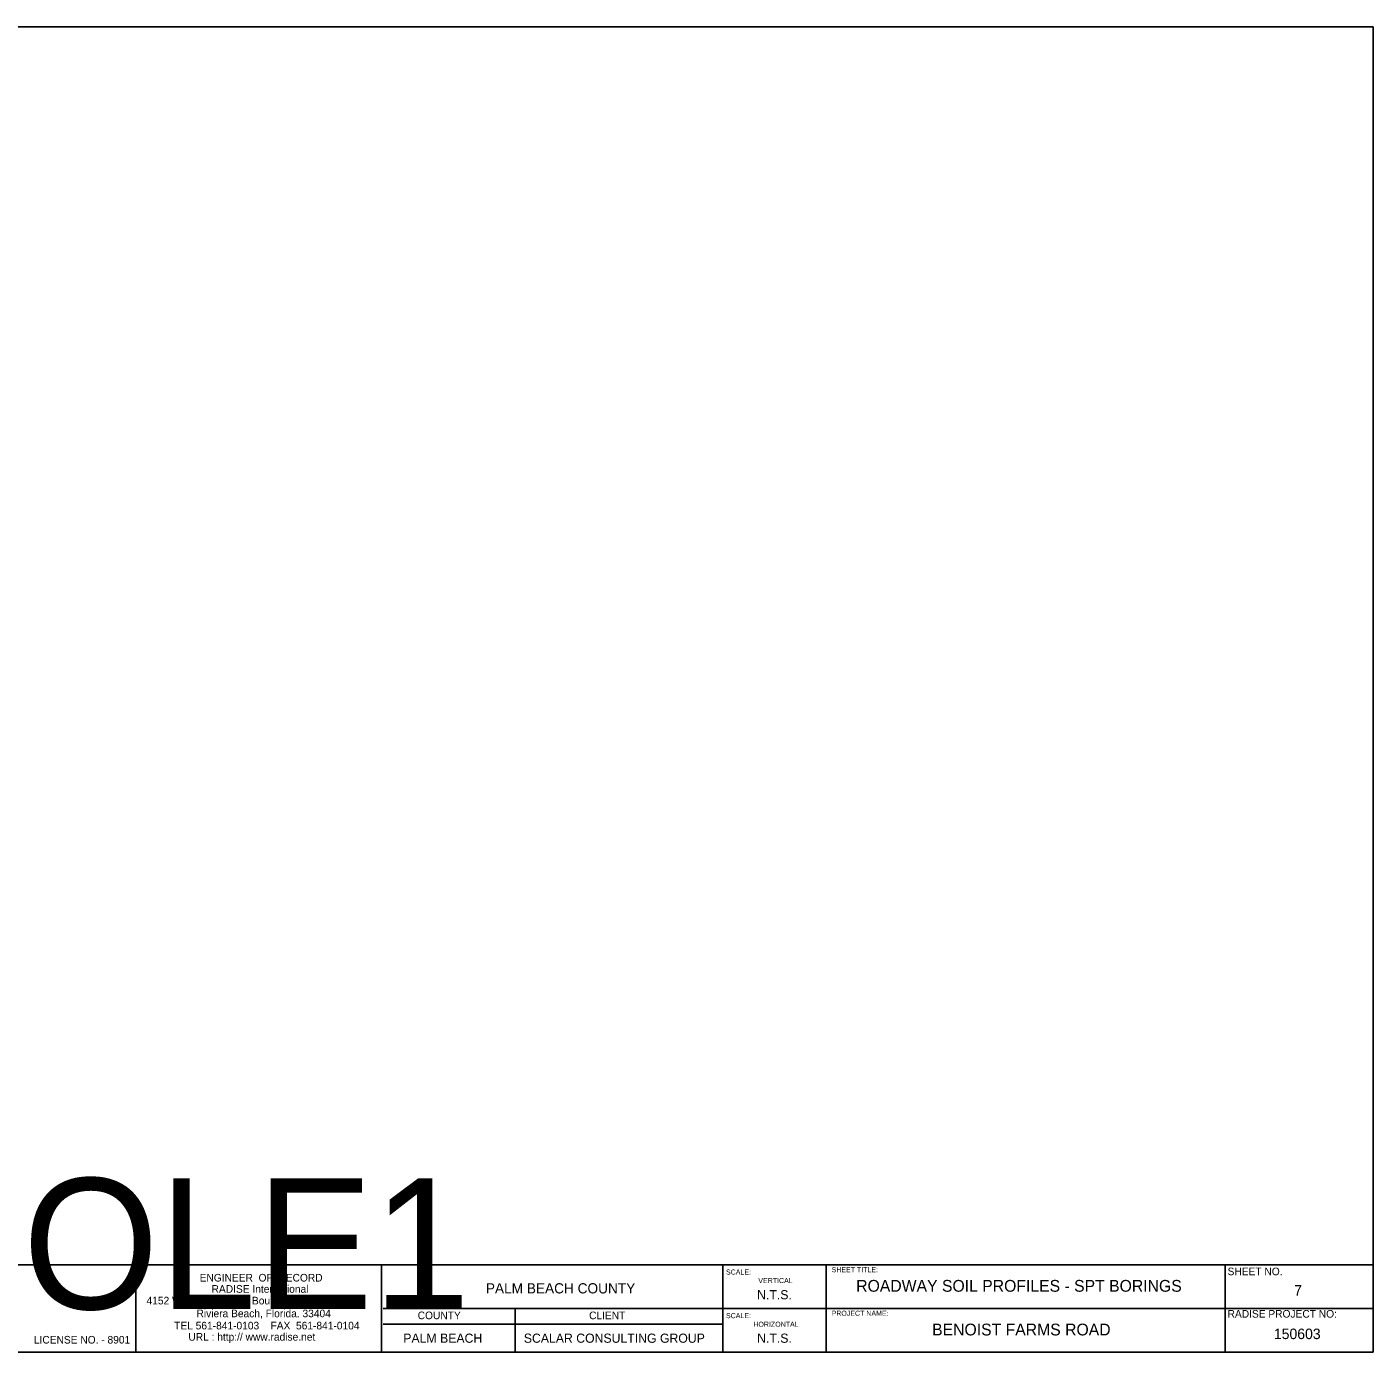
# Model space of a CAD drawing. Extents: x 0.6 to 16.4, y 0.2 to 10.3.
# Drawn here: x 6.16 to 16.45, y 0.16 to 10.29 of the extents above; entities that cross this region are included whole.
import ezdxf

# ---------------------------------------------------------------- set-up
doc = ezdxf.new("R2010")
doc.units = 0
for name, color, linetype in [('Level 1', 7, 'Continuous'), ('Level 23', 7, 'Continuous'), ('Level 24', 7, 'Continuous'), ('Level 46', 7, 'Continuous'), ('Level 63', 7, 'Continuous')]:
    doc.layers.add(name, color=color, linetype=linetype)

msp = doc.modelspace()

# ---------------------------------------------------------------- linework, layer by layer
at = {"layer": 'Level 23'}
for p, q in [((16.447, 0.161), (16.447, 10.287)), ((6.992, 0.161), (6.992, 0.827)), ((6.992, 0.161), (6.992, 0.827)), ((8.869, 0.161), (8.869, 0.827)), ((8.869, 0.161), (8.869, 0.827)), ((11.478, 0.161), (11.478, 0.827)), ((11.478, 0.161), (11.478, 0.827)), ((11.478, 0.161), (11.478, 0.827)), ((11.478, 0.161), (11.478, 0.827)), ((11.478, 0.161), (11.478, 0.827)), ((12.268, 0.161), (12.268, 0.827)), ((12.268, 0.161), (12.268, 0.827)), ((15.317, 0.161), (15.317, 0.827)), ((15.317, 0.161), (15.317, 0.827)), ((8.883, 0.494), (11.478, 0.494)), ((8.883, 0.494), (11.478, 0.494)), ((9.89, 0.494), (9.89, 0.161)), ((11.478, 0.494), (15.317, 0.494)), ((11.478, 0.494), (15.317, 0.494)), ((15.317, 0.494), (16.447, 0.494)), ((15.317, 0.494), (16.447, 0.494)), ((8.883, 0.373), (11.478, 0.373)), ((8.883, 0.373), (11.478, 0.373)), ((0.575, 0.161), (16.447, 0.161))]:
    msp.add_line(p, q, dxfattribs=at)
at = {"layer": 'Level 46'}
msp.add_line((0.573, 0.827), (16.447, 0.827), dxfattribs=at)
msp.add_line((0.573, 0.827), (16.447, 0.827), dxfattribs=at)
at = {"layer": 'Level 63'}
msp.add_lwpolyline([(0.575, 0.161), (16.447, 0.161), (16.447, 10.287), (0.575, 10.287), (0.575, 0.161)], dxfattribs=at)

# ---------------------------------------------------------------- texts
at = {"layer": 'Level 1'}
msp.add_text('OLE1', height=1, dxfattribs=at).set_placement((6.128, 0.489))
at = {"layer": 'Level 23'}
for s, height, p in [('ENGINEER  OF  RECORD', 0.05827, (7.48, 0.7)), ('SCALE:', 0.0389, (11.502, 0.753)), ('SCALE:', 0.0389, (11.502, 0.753)), ('SCALE:', 0.0389, (11.502, 0.753)), ('SCALE:', 0.0389, (11.502, 0.753)), ('SHEET TITLE:', 0.03887, (12.309, 0.771)), ('SHEET NO.', 0.0583, (15.335, 0.748)), ('RADISE International', 0.05827, (7.571, 0.614)), ('4152 West Blue Heron Boulevard, Suite 1114', 0.05827, (7.074, 0.525)), ('Riviera Beach, Florida. 33404', 0.05827, (7.456, 0.427)), ('COUNTY', 0.0583, (9.146, 0.412)), ('CLIENT', 0.0583, (10.456, 0.412)), ('SCALE:', 0.0389, (11.502, 0.42)), ('SCALE:', 0.0389, (11.502, 0.42)), ('SCALE:', 0.0389, (11.502, 0.42)), ('SCALE:', 0.0389, (11.502, 0.42)), ('PROJECT NAME:', 0.03887, (12.309, 0.438)), ('RADISE PROJECT NO:', 0.05827, (15.335, 0.424)), ('TEL 561-841-0103    FAX  561-841-0104', 0.05827, (7.285, 0.334)), ('                                                                URL : http:// www.radise.net', 0.05827, (6.008, 0.248)), ('LICENSE NO. - 8901', 0.05827, (6.213, 0.226))]:
    msp.add_text(s, height=height, dxfattribs=at).set_placement(p)
at = {"layer": 'Level 24'}
for s, height, p in [('VERTICAL', 0.0389, (11.749, 0.688)), ('PALM BEACH COUNTY ', 0.078, (9.667, 0.609)), ('N.T.S.', 0.07, (11.74, 0.564)), ('ROADWAY SOIL PROFILES - SPT BORINGS', 0.09, (12.497, 0.622)), ('7', 0.08, (15.844, 0.593)), ('HORIZONTAL', 0.0389, (11.711, 0.354)), ('BENOIST FARMS ROAD', 0.09, (13.077, 0.288)), ('150603', 0.08, (15.689, 0.26)), ('PALM BEACH', 0.07, (9.036, 0.232)), ('SCALAR CONSULTING GROUP', 0.07, (9.957, 0.232)), ('N.T.S.', 0.07, (11.74, 0.232))]:
    msp.add_text(s, height=height, dxfattribs=at).set_placement(p)

doc.saveas('drawing.dxf')
